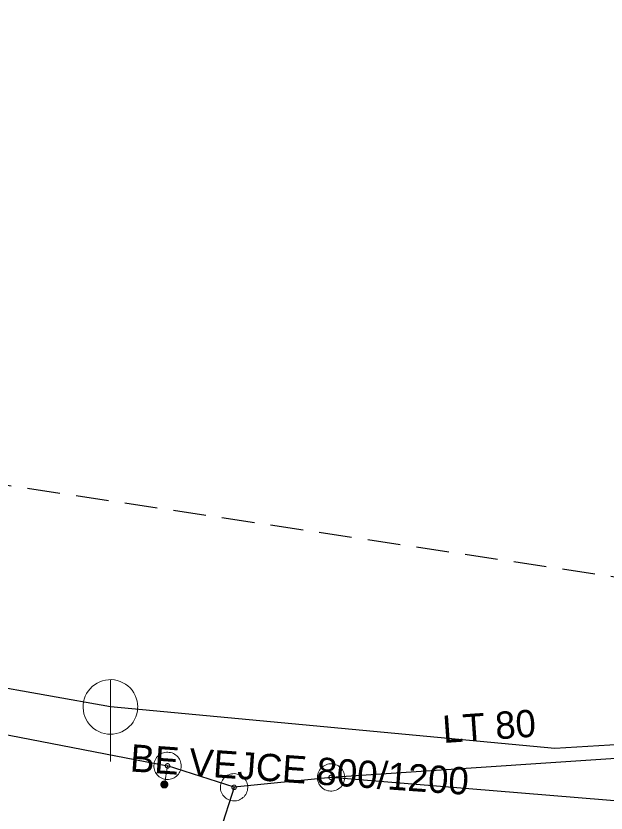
# Model space of a CAD drawing. Extents: x -725643 to -725418, y -978375 to -978221.
# Drawn here: x -725556.54 to -725534.94, y -978341.11 to -978311.92 of the extents above; entities that cross this region are included whole.
import ezdxf

# ---------------------------------------------------------------- set-up
doc = ezdxf.new("R2010")
doc.units = 0
doc.header["$LTSCALE"] = 0.4
doc.linetypes.add('MEDIUM_DASHED', pattern=[4.5, 3, -1.5])
doc.layers.add('1', color=7, linetype='Continuous')
for name, color, linetype, lineweight in [('14', 7, 'Continuous', 25), ('17', 7, 'Continuous', 25), ('22', 7, 'Continuous', 13), ('47', 7, 'Continuous', 13), ('63', 7, 'MEDIUM_DASHED', 25), ('9', 7, 'Continuous', 13)]:
    doc.layers.add(name, color=color, linetype=linetype, lineweight=lineweight)

msp = doc.modelspace()

# ---------------------------------------------------------------- linework, layer by layer
at = {"layer": '14', "lineweight": 13}
msp.add_line((-725550.989, -978339.387), (-725551.105, -978340.07), dxfattribs=at)
at = {"layer": '14'}
msp.add_lwpolyline([(-725527.513, -978334.331), (-725528.055, -978335.436), (-725528.703, -978336.338), (-725529.951, -978337.403), (-725531.603, -978338.206), (-725534.392, -978338.607), (-725536.813, -978338.747), (-725553.081, -978337.228), (-725592.702, -978330.168)], dxfattribs=at)
at = {"layer": '17'}
msp.add_line((-725548.553, -978340.172), (-725552.39, -978352.015), dxfattribs=at)
for points in [[(-725642.709, -978318.689), (-725622.261, -978324.109), (-725596.17, -978330.625), (-725550.989, -978339.387)], [(-725525.18, -978328.858), (-725526.883, -978336.403), (-725531.655, -978338.927), (-725545.003, -978339.812)], [(-725516.432, -978342.059), (-725524.989, -978341.46), (-725545.003, -978339.812), (-725548.553, -978340.172), (-725550.989, -978339.387)]]:
    msp.add_lwpolyline(points, dxfattribs=at)
at = {"layer": '22'}
msp.add_line((-725553.081, -978339.228), (-725553.08, -978336.228), dxfattribs=at)
msp.add_lwpolyline([(-725552.081, -978337.228), (-725552.086, -978337.119), (-725552.104, -978337.011), (-725552.134, -978336.905), (-725552.174, -978336.804), (-725552.226, -978336.707), (-725552.288, -978336.617), (-725552.36, -978336.534), (-725552.44, -978336.46), (-725552.528, -978336.394), (-725552.622, -978336.339), (-725552.722, -978336.294), (-725552.827, -978336.261), (-725552.934, -978336.239), (-725553.043, -978336.229), (-725553.153, -978336.231), (-725553.261, -978336.245), (-725553.368, -978336.27), (-725553.471, -978336.307), (-725553.569, -978336.356), (-725553.661, -978336.414), (-725553.747, -978336.483), (-725553.824, -978336.56), (-725553.893, -978336.646), (-725553.952, -978336.738), (-725554, -978336.836), (-725554.037, -978336.939), (-725554.063, -978337.046), (-725554.077, -978337.154), (-725554.08, -978337.264), (-725554.07, -978337.373), (-725554.049, -978337.48), (-725554.015, -978337.584), (-725553.971, -978337.684), (-725553.916, -978337.779), (-725553.85, -978337.867), (-725553.776, -978337.947), (-725553.693, -978338.019), (-725553.603, -978338.081), (-725553.507, -978338.133), (-725553.405, -978338.174), (-725553.3, -978338.204), (-725553.192, -978338.222), (-725553.082, -978338.228), (-725552.973, -978338.222), (-725552.865, -978338.204), (-725552.76, -978338.175), (-725552.658, -978338.134), (-725552.561, -978338.082), (-725552.471, -978338.02), (-725552.388, -978337.949), (-725552.313, -978337.869), (-725552.248, -978337.781), (-725552.192, -978337.687), (-725552.148, -978337.587), (-725552.114, -978337.483), (-725552.092, -978337.375), (-725552.082, -978337.266)], close=True, dxfattribs=at)
at = {"layer": '47'}
for points in [[(-725550.489, -978339.398), (-725550.49, -978339.346), (-725550.497, -978339.293), (-725550.51, -978339.243), (-725550.527, -978339.194), (-725550.55, -978339.146), (-725550.578, -978339.102), (-725550.61, -978339.061), (-725550.646, -978339.023), (-725550.686, -978338.989), (-725550.729, -978338.959), (-725550.775, -978338.934), (-725550.824, -978338.915), (-725550.874, -978338.9), (-725550.925, -978338.891), (-725550.977, -978338.887), (-725551.029, -978338.888), (-725551.082, -978338.895), (-725551.133, -978338.908), (-725551.181, -978338.925), (-725551.229, -978338.948), (-725551.273, -978338.976), (-725551.315, -978339.008), (-725551.353, -978339.044), (-725551.387, -978339.084), (-725551.416, -978339.127), (-725551.441, -978339.173), (-725551.461, -978339.222), (-725551.475, -978339.272), (-725551.484, -978339.323), (-725551.488, -978339.375), (-725551.487, -978339.427), (-725551.48, -978339.48), (-725551.468, -978339.531), (-725551.45, -978339.579), (-725551.427, -978339.627), (-725551.4, -978339.671), (-725551.368, -978339.713), (-725551.332, -978339.751), (-725551.291, -978339.785), (-725551.248, -978339.814), (-725551.202, -978339.839), (-725551.154, -978339.859), (-725551.103, -978339.873), (-725551.052, -978339.882), (-725551, -978339.886), (-725550.948, -978339.885), (-725550.895, -978339.878), (-725550.845, -978339.866), (-725550.796, -978339.848), (-725550.748, -978339.825), (-725550.704, -978339.798), (-725550.663, -978339.766), (-725550.625, -978339.73), (-725550.591, -978339.689), (-725550.561, -978339.646), (-725550.536, -978339.6), (-725550.517, -978339.552), (-725550.502, -978339.501), (-725550.493, -978339.45)], [(-725550.907, -978339.388), (-725550.906, -978339.379), (-725550.908, -978339.371), (-725550.91, -978339.363), (-725550.913, -978339.355), (-725550.917, -978339.347), (-725550.921, -978339.34), (-725550.926, -978339.333), (-725550.932, -978339.327), (-725550.939, -978339.322), (-725550.946, -978339.316), (-725550.954, -978339.312), (-725550.962, -978339.309), (-725550.97, -978339.307), (-725550.978, -978339.305), (-725550.987, -978339.305), (-725550.996, -978339.304), (-725551.004, -978339.306), (-725551.012, -978339.308), (-725551.02, -978339.311), (-725551.028, -978339.315), (-725551.035, -978339.319), (-725551.042, -978339.324), (-725551.048, -978339.33), (-725551.054, -978339.337), (-725551.059, -978339.344), (-725551.063, -978339.352), (-725551.066, -978339.36), (-725551.068, -978339.368), (-725551.07, -978339.376), (-725551.07, -978339.385), (-725551.071, -978339.394), (-725551.069, -978339.402), (-725551.067, -978339.41), (-725551.064, -978339.418), (-725551.06, -978339.426), (-725551.057, -978339.433), (-725551.051, -978339.44), (-725551.045, -978339.446), (-725551.038, -978339.452), (-725551.031, -978339.457), (-725551.023, -978339.461), (-725551.015, -978339.464), (-725551.007, -978339.466), (-725550.999, -978339.468), (-725550.99, -978339.468), (-725550.981, -978339.469), (-725550.973, -978339.467), (-725550.965, -978339.465), (-725550.957, -978339.462), (-725550.949, -978339.458), (-725550.942, -978339.455), (-725550.935, -978339.449), (-725550.929, -978339.443), (-725550.924, -978339.436), (-725550.918, -978339.429), (-725550.914, -978339.421), (-725550.911, -978339.413), (-725550.909, -978339.405), (-725550.907, -978339.397)], [(-725544.509, -978339.728), (-725544.521, -978339.678), (-725544.538, -978339.628), (-725544.56, -978339.581), (-725544.586, -978339.535), (-725544.617, -978339.493), (-725544.653, -978339.454), (-725544.692, -978339.42), (-725544.735, -978339.39), (-725544.78, -978339.364), (-725544.828, -978339.343), (-725544.878, -978339.327), (-725544.93, -978339.318), (-725544.981, -978339.312), (-725545.034, -978339.313), (-725545.086, -978339.318), (-725545.136, -978339.33), (-725545.186, -978339.347), (-725545.234, -978339.369), (-725545.279, -978339.395), (-725545.321, -978339.426), (-725545.36, -978339.462), (-725545.395, -978339.501), (-725545.425, -978339.544), (-725545.451, -978339.589), (-725545.471, -978339.637), (-725545.487, -978339.687), (-725545.497, -978339.739), (-725545.502, -978339.79), (-725545.501, -978339.843), (-725545.496, -978339.895), (-725545.484, -978339.945), (-725545.467, -978339.995), (-725545.446, -978340.043), (-725545.419, -978340.088), (-725545.388, -978340.13), (-725545.353, -978340.169), (-725545.314, -978340.204), (-725545.271, -978340.234), (-725545.225, -978340.26), (-725545.177, -978340.28), (-725545.127, -978340.296), (-725545.076, -978340.307), (-725545.024, -978340.311), (-725544.971, -978340.31), (-725544.919, -978340.305), (-725544.869, -978340.293), (-725544.819, -978340.276), (-725544.772, -978340.255), (-725544.726, -978340.228), (-725544.684, -978340.197), (-725544.645, -978340.162), (-725544.611, -978340.123), (-725544.581, -978340.08), (-725544.555, -978340.034), (-725544.534, -978339.986), (-725544.518, -978339.936), (-725544.508, -978339.885), (-725544.503, -978339.833), (-725544.504, -978339.78)], [(-725548.053, -978340.183), (-725548.054, -978340.131), (-725548.061, -978340.078), (-725548.074, -978340.028), (-725548.091, -978339.979), (-725548.114, -978339.931), (-725548.142, -978339.887), (-725548.174, -978339.846), (-725548.21, -978339.808), (-725548.25, -978339.774), (-725548.293, -978339.744), (-725548.339, -978339.719), (-725548.388, -978339.7), (-725548.438, -978339.685), (-725548.489, -978339.676), (-725548.541, -978339.672), (-725548.593, -978339.673), (-725548.646, -978339.68), (-725548.697, -978339.693), (-725548.745, -978339.71), (-725548.793, -978339.733), (-725548.837, -978339.761), (-725548.879, -978339.793), (-725548.917, -978339.829), (-725548.951, -978339.869), (-725548.98, -978339.912), (-725549.005, -978339.958), (-725549.025, -978340.007), (-725549.039, -978340.057), (-725549.048, -978340.108), (-725549.052, -978340.16), (-725549.051, -978340.212), (-725549.044, -978340.265), (-725549.032, -978340.316), (-725549.014, -978340.364), (-725548.991, -978340.412), (-725548.964, -978340.456), (-725548.932, -978340.498), (-725548.896, -978340.536), (-725548.855, -978340.57), (-725548.812, -978340.599), (-725548.766, -978340.624), (-725548.718, -978340.644), (-725548.667, -978340.658), (-725548.616, -978340.667), (-725548.564, -978340.671), (-725548.512, -978340.67), (-725548.459, -978340.663), (-725548.409, -978340.651), (-725548.36, -978340.633), (-725548.312, -978340.61), (-725548.268, -978340.583), (-725548.227, -978340.551), (-725548.189, -978340.515), (-725548.155, -978340.474), (-725548.125, -978340.431), (-725548.1, -978340.385), (-725548.081, -978340.337), (-725548.066, -978340.286), (-725548.057, -978340.235)], [(-725544.922, -978339.798), (-725544.923, -978339.789), (-725544.926, -978339.781), (-725544.93, -978339.774), (-725544.934, -978339.766), (-725544.939, -978339.759), (-725544.945, -978339.753), (-725544.951, -978339.747), (-725544.958, -978339.742), (-725544.966, -978339.738), (-725544.974, -978339.735), (-725544.982, -978339.732), (-725544.991, -978339.73), (-725544.999, -978339.73), (-725545.007, -978339.729), (-725545.016, -978339.731), (-725545.025, -978339.732), (-725545.033, -978339.735), (-725545.04, -978339.739), (-725545.048, -978339.743), (-725545.055, -978339.748), (-725545.061, -978339.754), (-725545.067, -978339.76), (-725545.072, -978339.767), (-725545.077, -978339.775), (-725545.079, -978339.783), (-725545.082, -978339.791), (-725545.084, -978339.8), (-725545.084, -978339.808), (-725545.085, -978339.816), (-725545.083, -978339.825), (-725545.082, -978339.834), (-725545.079, -978339.842), (-725545.075, -978339.849), (-725545.071, -978339.857), (-725545.066, -978339.864), (-725545.061, -978339.87), (-725545.054, -978339.876), (-725545.047, -978339.881), (-725545.039, -978339.886), (-725545.031, -978339.888), (-725545.023, -978339.891), (-725545.014, -978339.893), (-725545.006, -978339.893), (-725544.998, -978339.894), (-725544.989, -978339.892), (-725544.98, -978339.891), (-725544.972, -978339.888), (-725544.965, -978339.884), (-725544.957, -978339.88), (-725544.95, -978339.875), (-725544.944, -978339.87), (-725544.938, -978339.863), (-725544.933, -978339.856), (-725544.929, -978339.848), (-725544.926, -978339.84), (-725544.923, -978339.832), (-725544.921, -978339.823), (-725544.921, -978339.815), (-725544.92, -978339.807)], [(-725548.471, -978340.173), (-725548.47, -978340.164), (-725548.472, -978340.156), (-725548.474, -978340.148), (-725548.477, -978340.14), (-725548.481, -978340.132), (-725548.485, -978340.125), (-725548.49, -978340.118), (-725548.496, -978340.112), (-725548.503, -978340.107), (-725548.51, -978340.101), (-725548.518, -978340.097), (-725548.526, -978340.094), (-725548.534, -978340.092), (-725548.542, -978340.09), (-725548.551, -978340.09), (-725548.56, -978340.089), (-725548.568, -978340.091), (-725548.576, -978340.093), (-725548.584, -978340.096), (-725548.592, -978340.1), (-725548.599, -978340.104), (-725548.606, -978340.109), (-725548.612, -978340.115), (-725548.618, -978340.122), (-725548.623, -978340.129), (-725548.627, -978340.137), (-725548.63, -978340.145), (-725548.632, -978340.153), (-725548.634, -978340.161), (-725548.634, -978340.17), (-725548.635, -978340.179), (-725548.633, -978340.187), (-725548.631, -978340.195), (-725548.628, -978340.203), (-725548.624, -978340.211), (-725548.621, -978340.218), (-725548.615, -978340.225), (-725548.609, -978340.231), (-725548.602, -978340.237), (-725548.595, -978340.242), (-725548.587, -978340.246), (-725548.579, -978340.249), (-725548.571, -978340.251), (-725548.563, -978340.253), (-725548.554, -978340.253), (-725548.545, -978340.254), (-725548.537, -978340.252), (-725548.529, -978340.25), (-725548.521, -978340.247), (-725548.513, -978340.243), (-725548.506, -978340.24), (-725548.499, -978340.234), (-725548.493, -978340.228), (-725548.488, -978340.221), (-725548.482, -978340.214), (-725548.478, -978340.206), (-725548.475, -978340.198), (-725548.473, -978340.19), (-725548.471, -978340.182)]]:
    msp.add_lwpolyline(points, close=True, dxfattribs=at)
at = {"layer": '63'}
msp.add_lwpolyline([(-725440.663, -978348.762), (-725504.582, -978352.39), (-725504.582, -978352.39), (-725528.587, -978359.368), (-725528.587, -978359.368), (-725551.474, -978371.929), (-725551.474, -978371.929), (-725566.826, -978360.206), (-725566.826, -978360.206), (-725557.894, -978328.944), (-725533.89, -978332.573), (-725533.89, -978332.573), (-725529.424, -978311.918), (-725529.424, -978311.918), (-725514.351, -978316.105), (-725514.351, -978316.105), (-725517.422, -978329.502), (-725517.422, -978329.502), (-725504.582, -978332.573), (-725504.582, -978332.573), (-725495.092, -978321.408)], dxfattribs=at)
at = {"layer": '9'}
for points in [[(-725551.231, -978340.07), (-725551.231, -978340.083), (-725551.228, -978340.096), (-725551.226, -978340.109), (-725551.221, -978340.121), (-725551.215, -978340.133), (-725551.208, -978340.144), (-725551.2, -978340.154), (-725551.19, -978340.164), (-725551.179, -978340.172), (-725551.169, -978340.179), (-725551.157, -978340.185), (-725551.145, -978340.19), (-725551.132, -978340.193), (-725551.119, -978340.195), (-725551.106, -978340.197), (-725551.093, -978340.196), (-725551.08, -978340.194), (-725551.067, -978340.191), (-725551.054, -978340.186), (-725551.043, -978340.18), (-725551.032, -978340.173), (-725551.022, -978340.165), (-725551.012, -978340.155), (-725551.004, -978340.145), (-725550.997, -978340.134), (-725550.991, -978340.122), (-725550.986, -978340.11), (-725550.983, -978340.097), (-725550.981, -978340.084), (-725550.978, -978340.071), (-725550.98, -978340.058), (-725550.982, -978340.045), (-725550.985, -978340.032), (-725550.99, -978340.02), (-725550.995, -978340.008), (-725551.003, -978339.997), (-725551.011, -978339.987), (-725551.021, -978339.977), (-725551.031, -978339.969), (-725551.042, -978339.962), (-725551.054, -978339.956), (-725551.066, -978339.951), (-725551.079, -978339.948), (-725551.092, -978339.946), (-725551.105, -978339.945), (-725551.118, -978339.945), (-725551.13, -978339.947), (-725551.144, -978339.95), (-725551.156, -978339.955), (-725551.168, -978339.961), (-725551.179, -978339.968), (-725551.189, -978339.976), (-725551.199, -978339.986), (-725551.206, -978339.996), (-725551.214, -978340.007), (-725551.22, -978340.019), (-725551.225, -978340.031), (-725551.228, -978340.044), (-725551.23, -978340.057)], [(-725551.211, -978340.07), (-725551.212, -978340.081), (-725551.21, -978340.092), (-725551.206, -978340.103), (-725551.203, -978340.113), (-725551.198, -978340.123), (-725551.192, -978340.132), (-725551.184, -978340.141), (-725551.177, -978340.149), (-725551.168, -978340.156), (-725551.159, -978340.162), (-725551.149, -978340.167), (-725551.139, -978340.171), (-725551.128, -978340.174), (-725551.117, -978340.177), (-725551.106, -978340.177), (-725551.095, -978340.177), (-725551.084, -978340.175), (-725551.073, -978340.172), (-725551.063, -978340.168), (-725551.053, -978340.163), (-725551.044, -978340.157), (-725551.035, -978340.15), (-725551.027, -978340.142), (-725551.02, -978340.133), (-725551.014, -978340.124), (-725551.009, -978340.114), (-725551.005, -978340.104), (-725551.002, -978340.093), (-725551, -978340.082), (-725550.999, -978340.071), (-725550.999, -978340.06), (-725551, -978340.049), (-725551.004, -978340.038), (-725551.008, -978340.028), (-725551.013, -978340.018), (-725551.019, -978340.009), (-725551.026, -978340), (-725551.034, -978339.992), (-725551.043, -978339.985), (-725551.052, -978339.979), (-725551.062, -978339.974), (-725551.071, -978339.97), (-725551.083, -978339.967), (-725551.093, -978339.965), (-725551.105, -978339.965), (-725551.116, -978339.964), (-725551.127, -978339.966), (-725551.138, -978339.969), (-725551.147, -978339.973), (-725551.157, -978339.978), (-725551.167, -978339.984), (-725551.176, -978339.991), (-725551.184, -978339.999), (-725551.191, -978340.008), (-725551.196, -978340.017), (-725551.201, -978340.027), (-725551.206, -978340.037), (-725551.209, -978340.048), (-725551.211, -978340.059)], [(-725551.192, -978340.07), (-725551.192, -978340.079), (-725551.191, -978340.088), (-725551.188, -978340.097), (-725551.184, -978340.105), (-725551.181, -978340.113), (-725551.176, -978340.121), (-725551.169, -978340.128), (-725551.164, -978340.134), (-725551.157, -978340.14), (-725551.149, -978340.145), (-725551.141, -978340.149), (-725551.133, -978340.152), (-725551.124, -978340.155), (-725551.115, -978340.156), (-725551.106, -978340.158), (-725551.097, -978340.157), (-725551.088, -978340.156), (-725551.079, -978340.153), (-725551.071, -978340.15), (-725551.063, -978340.146), (-725551.054, -978340.141), (-725551.048, -978340.135), (-725551.042, -978340.129), (-725551.036, -978340.122), (-725551.031, -978340.114), (-725551.027, -978340.106), (-725551.024, -978340.098), (-725551.021, -978340.089), (-725551.02, -978340.08), (-725551.017, -978340.071), (-725551.019, -978340.062), (-725551.02, -978340.053), (-725551.022, -978340.044), (-725551.026, -978340.036), (-725551.03, -978340.028), (-725551.035, -978340.02), (-725551.041, -978340.013), (-725551.047, -978340.007), (-725551.054, -978340.001), (-725551.062, -978339.996), (-725551.07, -978339.992), (-725551.078, -978339.989), (-725551.087, -978339.986), (-725551.096, -978339.985), (-725551.105, -978339.984), (-725551.114, -978339.984), (-725551.123, -978339.985), (-725551.132, -978339.988), (-725551.14, -978339.991), (-725551.147, -978339.995), (-725551.156, -978340), (-725551.163, -978340.006), (-725551.169, -978340.012), (-725551.174, -978340.019), (-725551.179, -978340.027), (-725551.184, -978340.035), (-725551.187, -978340.043), (-725551.19, -978340.052), (-725551.191, -978340.061)], [(-725551.172, -978340.07), (-725551.172, -978340.077), (-725551.171, -978340.084), (-725551.169, -978340.091), (-725551.167, -978340.097), (-725551.164, -978340.103), (-725551.16, -978340.109), (-725551.156, -978340.115), (-725551.151, -978340.12), (-725551.145, -978340.124), (-725551.139, -978340.128), (-725551.133, -978340.131), (-725551.127, -978340.134), (-725551.12, -978340.135), (-725551.113, -978340.138), (-725551.106, -978340.138), (-725551.098, -978340.138), (-725551.092, -978340.136), (-725551.085, -978340.135), (-725551.079, -978340.132), (-725551.071, -978340.129), (-725551.067, -978340.125), (-725551.061, -978340.121), (-725551.056, -978340.116), (-725551.052, -978340.11), (-725551.048, -978340.104), (-725551.044, -978340.098), (-725551.042, -978340.092), (-725551.04, -978340.085), (-725551.039, -978340.078), (-725551.038, -978340.071), (-725551.038, -978340.064), (-725551.039, -978340.057), (-725551.041, -978340.05), (-725551.044, -978340.044), (-725551.047, -978340.037), (-725551.051, -978340.032), (-725551.054, -978340.026), (-725551.059, -978340.021), (-725551.066, -978340.017), (-725551.071, -978340.013), (-725551.078, -978340.01), (-725551.084, -978340.007), (-725551.091, -978340.005), (-725551.098, -978340.004), (-725551.105, -978340.004), (-725551.112, -978340.004), (-725551.119, -978340.004), (-725551.125, -978340.006), (-725551.132, -978340.009), (-725551.138, -978340.012), (-725551.144, -978340.016), (-725551.15, -978340.02), (-725551.155, -978340.025), (-725551.159, -978340.031), (-725551.163, -978340.036), (-725551.166, -978340.043), (-725551.169, -978340.049), (-725551.169, -978340.056), (-725551.172, -978340.063)], [(-725551.152, -978340.07), (-725551.152, -978340.075), (-725551.152, -978340.08), (-725551.151, -978340.085), (-725551.149, -978340.089), (-725551.147, -978340.094), (-725551.144, -978340.098), (-725551.141, -978340.101), (-725551.137, -978340.105), (-725551.134, -978340.108), (-725551.13, -978340.111), (-725551.125, -978340.113), (-725551.12, -978340.115), (-725551.116, -978340.116), (-725551.111, -978340.118), (-725551.106, -978340.118), (-725551.101, -978340.118), (-725551.096, -978340.117), (-725551.091, -978340.116), (-725551.087, -978340.114), (-725551.081, -978340.112), (-725551.078, -978340.109), (-725551.074, -978340.106), (-725551.071, -978340.102), (-725551.068, -978340.099), (-725551.065, -978340.095), (-725551.063, -978340.09), (-725551.061, -978340.086), (-725551.059, -978340.081), (-725551.059, -978340.076), (-725551.058, -978340.071), (-725551.058, -978340.066), (-725551.059, -978340.061), (-725551.059, -978340.056), (-725551.062, -978340.052), (-725551.064, -978340.047), (-725551.067, -978340.043), (-725551.07, -978340.039), (-725551.073, -978340.036), (-725551.076, -978340.033), (-725551.081, -978340.03), (-725551.086, -978340.028), (-725551.09, -978340.026), (-725551.095, -978340.025), (-725551.1, -978340.024), (-725551.105, -978340.024), (-725551.11, -978340.024), (-725551.115, -978340.025), (-725551.12, -978340.025), (-725551.124, -978340.027), (-725551.129, -978340.029), (-725551.133, -978340.032), (-725551.136, -978340.035), (-725551.14, -978340.038), (-725551.142, -978340.042), (-725551.146, -978340.046), (-725551.147, -978340.051), (-725551.15, -978340.055), (-725551.151, -978340.06), (-725551.152, -978340.065)], [(-725551.132, -978340.07), (-725551.132, -978340.073), (-725551.133, -978340.076), (-725551.132, -978340.078), (-725551.13, -978340.081), (-725551.13, -978340.084), (-725551.128, -978340.086), (-725551.125, -978340.088), (-725551.124, -978340.09), (-725551.122, -978340.092), (-725551.12, -978340.094), (-725551.117, -978340.096), (-725551.114, -978340.097), (-725551.112, -978340.097), (-725551.108, -978340.098), (-725551.106, -978340.098), (-725551.103, -978340.098), (-725551.1, -978340.098), (-725551.097, -978340.097), (-725551.095, -978340.096), (-725551.092, -978340.095), (-725551.09, -978340.093), (-725551.087, -978340.091), (-725551.085, -978340.089), (-725551.084, -978340.087), (-725551.081, -978340.085), (-725551.081, -978340.082), (-725551.079, -978340.079), (-725551.079, -978340.077), (-725551.078, -978340.074), (-725551.076, -978340.071), (-725551.078, -978340.068), (-725551.078, -978340.065), (-725551.079, -978340.062), (-725551.08, -978340.06), (-725551.081, -978340.057), (-725551.083, -978340.055), (-725551.084, -978340.052), (-725551.086, -978340.05), (-725551.089, -978340.049), (-725551.091, -978340.047), (-725551.093, -978340.046), (-725551.096, -978340.045), (-725551.098, -978340.044), (-725551.102, -978340.044), (-725551.105, -978340.043), (-725551.108, -978340.044), (-725551.111, -978340.043), (-725551.113, -978340.045), (-725551.116, -978340.045), (-725551.119, -978340.046), (-725551.12, -978340.048), (-725551.123, -978340.049), (-725551.125, -978340.051), (-725551.127, -978340.054), (-725551.129, -978340.056), (-725551.13, -978340.059), (-725551.13, -978340.061), (-725551.132, -978340.064), (-725551.132, -978340.067)], [(-725551.113, -978340.07), (-725551.113, -978340.072), (-725551.113, -978340.072), (-725551.112, -978340.072), (-725551.112, -978340.074), (-725551.113, -978340.075), (-725551.111, -978340.075), (-725551.111, -978340.075), (-725551.111, -978340.077), (-725551.111, -978340.077), (-725551.11, -978340.078), (-725551.108, -978340.078), (-725551.108, -978340.078), (-725551.108, -978340.079), (-725551.106, -978340.079), (-725551.106, -978340.079), (-725551.105, -978340.079), (-725551.103, -978340.079), (-725551.103, -978340.078), (-725551.103, -978340.078), (-725551.101, -978340.078), (-725551.101, -978340.077), (-725551.101, -978340.077), (-725551.1, -978340.076), (-725551.1, -978340.076), (-725551.098, -978340.075), (-725551.098, -978340.074), (-725551.097, -978340.073), (-725551.097, -978340.073), (-725551.097, -978340.072), (-725551.097, -978340.071), (-725551.097, -978340.07), (-725551.097, -978340.069), (-725551.097, -978340.069), (-725551.098, -978340.068), (-725551.098, -978340.067), (-725551.098, -978340.066), (-725551.098, -978340.066), (-725551.1, -978340.065), (-725551.1, -978340.065), (-725551.101, -978340.064), (-725551.102, -978340.064), (-725551.103, -978340.063), (-725551.103, -978340.063), (-725551.103, -978340.063), (-725551.105, -978340.063), (-725551.106, -978340.063), (-725551.107, -978340.063), (-725551.107, -978340.063), (-725551.108, -978340.064), (-725551.108, -978340.063), (-725551.11, -978340.065), (-725551.11, -978340.065), (-725551.111, -978340.065), (-725551.111, -978340.065), (-725551.112, -978340.067), (-725551.112, -978340.068), (-725551.112, -978340.069), (-725551.113, -978340.069), (-725551.113, -978340.07)]]:
    msp.add_lwpolyline(points, close=True, dxfattribs=at)

# ---------------------------------------------------------------- texts
at = {"layer": '1'}
for s, rotation, p in [('LT 80 ', 4, (-725540.888, -978338.551)), ('BE VEJCE 800/1200 ', 356, (-725552.382, -978339.588))]:
    msp.add_text(s, height=1, rotation=rotation, dxfattribs=at).set_placement(p)

doc.saveas('drawing.dxf')
